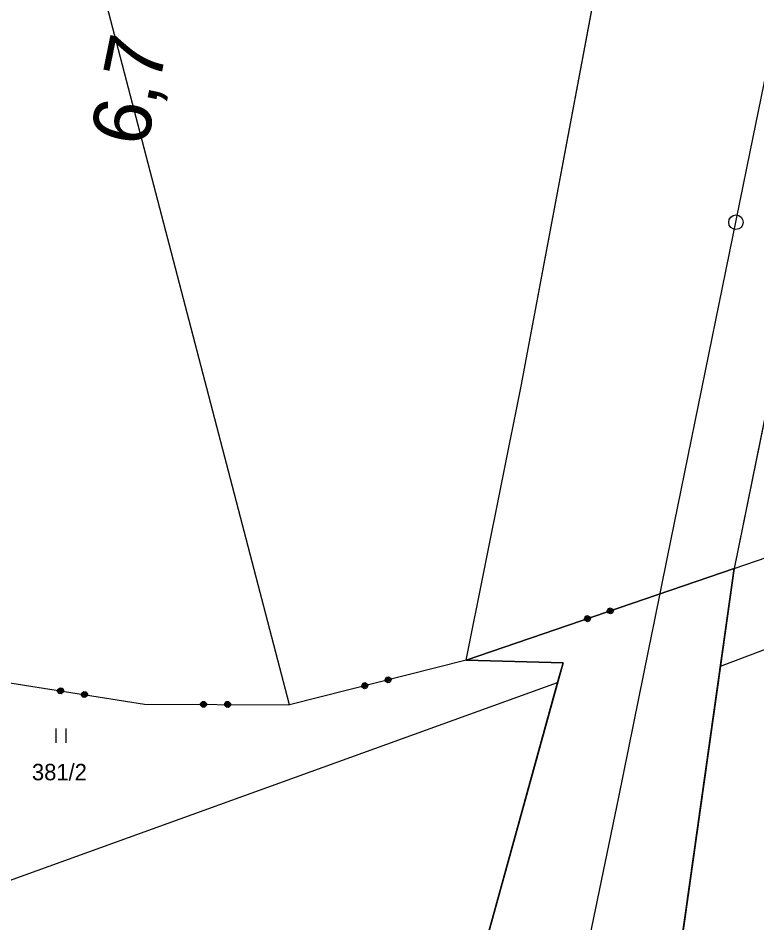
# Model space of a CAD drawing. Extents: x -866656 to -858817, y -1041816 to -1038653.
# Drawn here: x -864198.3 to -864121.9, y -1040985.3 to -1040891.7 of the extents above; entities that cross this region are included whole.
import ezdxf

# ---------------------------------------------------------------- set-up
doc = ezdxf.new("R2010")
doc.units = 0
for name, color, linetype in [('SZDC', 7, 'Continuous'), ('Vrstva 1', 7, 'Continuous'), ('Vrstva 3', 7, 'Continuous'), ('Vrstva 53', 7, 'Continuous'), ('Vrstva 7', 7, 'Continuous')]:
    doc.layers.add(name, color=color, linetype=linetype)

msp = doc.modelspace()

# ---------------------------------------------------------------- linework, layer by layer
at = {"layer": 'SZDC'}
for points in [[(-864079.126, -1040751.242), (-864090.668, -1040816.123), (-864108.728, -1040902.454), (-864114.595, -1040901.24), (-864124.203, -1040948.655), (-864151.935, -1040958.113), (-864146.262, -1040929.775), (-864137.277, -1040882.02), (-864125.279, -1040805.207)], [(-864192.472, -1041180.21), (-864181.025, -1041111.422), (-864180.31, -1041090.767), (-864179.792, -1041075.794), (-864171.697, -1041056.539), (-864163.891, -1041037.972), (-864142.486, -1040960.447), (-864141.92, -1040958.397), (-864151.935, -1040958.113), (-864124.203, -1040948.655), (-864125.631, -1040958.765), (-864138.225, -1041047.925), (-864138.655, -1041084.258), (-864136.94, -1041093.856), (-864135.28, -1041103.15), (-864140.045, -1041118.732), (-864153.013, -1041128.827)]]:
    msp.add_lwpolyline(points, dxfattribs=at)
at = {"layer": 'Vrstva 1'}
for p, q in [((-864170.25, -1040962.74), (-864192.213, -1040878.627)), ((-864146.262, -1040929.775), (-864137.277, -1040882.02)), ((-864114.595, -1040901.24), (-864124.203, -1040948.655)), ((-864151.935, -1040958.113), (-864146.262, -1040929.775)), ((-864138.225, -1041047.925), (-864124.203, -1040948.655)), ((-864125.631, -1040958.765), (-864102.97, -1040950.08)), ((-864141.92, -1040958.397), (-864163.891, -1041037.972)), ((-864151.935, -1040958.113), (-864141.92, -1040958.397)), ((-864202.71, -1040982.19), (-864142.486, -1040960.447)), ((-864194.4, -1040966.69), (-864194.4, -1040965.19)), ((-864193.4, -1040965.19), (-864193.4, -1040966.69))]:
    msp.add_line(p, q, dxfattribs=at)
msp.add_lwpolyline([(-864190.897, -1041239.893), (-864187.654, -1041224.26), (-864179.077, -1041182.252), (-864176.192, -1041168.165), (-864167.631, -1041126.213), (-864158.946, -1041083.668), (-864157.987, -1041079.013), (-864156.213, -1041070.305), (-864147.519, -1041027.821), (-864138.927, -1040985.783), (-864136.16, -1040972.299), (-864133.068, -1040957.148), (-864132.451, -1040954.143), (-864131.095, -1040947.46), (-864122.536, -1040905.522), (-864114.141, -1040864.418), (-864106.236, -1040825.758)], dxfattribs=at)
at = {"layer": 'Vrstva 3'}
for p, q in [((-864124.203, -1040948.655), (-864108.814, -1040943.274)), ((-864124.203, -1040948.655), (-864108.814, -1040943.274)), ((-864124.203, -1040948.655), (-864151.935, -1040958.113)), ((-864124.203, -1040948.655), (-864151.935, -1040958.113)), ((-864137.344, -1040953.031), (-864137.219, -1040952.777)), ((-864137.344, -1040953.031), (-864137.219, -1040952.777)), ((-864137.28, -1040953.221), (-864137.344, -1040953.031)), ((-864137.28, -1040953.221), (-864137.344, -1040953.031)), ((-864137.249, -1040952.999), (-864137.185, -1040953.188)), ((-864137.249, -1040952.999), (-864137.185, -1040953.188)), ((-864137.219, -1040952.777), (-864137.03, -1040952.713)), ((-864137.219, -1040952.777), (-864137.03, -1040952.713)), ((-864137.187, -1040952.872), (-864136.998, -1040952.808)), ((-864137.187, -1040952.872), (-864136.998, -1040952.808)), ((-864137.058, -1040953.251), (-864137.187, -1040952.872)), ((-864137.058, -1040953.251), (-864137.187, -1040952.872)), ((-864137.092, -1040952.84), (-864136.963, -1040953.218)), ((-864137.092, -1040952.84), (-864136.963, -1040953.218)), ((-864137.03, -1040952.713), (-864136.776, -1040952.838)), ((-864137.03, -1040952.713), (-864136.776, -1040952.838)), ((-864136.998, -1040952.808), (-864136.869, -1040953.186)), ((-864136.998, -1040952.808), (-864136.869, -1040953.186)), ((-864136.806, -1040953.059), (-864136.871, -1040952.87)), ((-864136.806, -1040953.059), (-864136.871, -1040952.87)), ((-864136.869, -1040953.186), (-864136.806, -1040953.059)), ((-864136.869, -1040953.186), (-864136.806, -1040953.059)), ((-864136.712, -1040953.027), (-864136.836, -1040953.281)), ((-864136.712, -1040953.027), (-864136.836, -1040953.281)), ((-864136.776, -1040952.838), (-864136.712, -1040953.027)), ((-864136.776, -1040952.838), (-864136.712, -1040953.027)), ((-864139.71, -1040953.838), (-864139.586, -1040953.584)), ((-864139.71, -1040953.838), (-864139.586, -1040953.584)), ((-864139.646, -1040954.028), (-864139.71, -1040953.838)), ((-864139.646, -1040954.028), (-864139.71, -1040953.838)), ((-864139.616, -1040953.806), (-864139.551, -1040953.995)), ((-864139.616, -1040953.806), (-864139.551, -1040953.995)), ((-864139.586, -1040953.584), (-864139.396, -1040953.52)), ((-864139.586, -1040953.584), (-864139.396, -1040953.52)), ((-864139.553, -1040953.679), (-864139.364, -1040953.615)), ((-864139.553, -1040953.679), (-864139.364, -1040953.615)), ((-864139.424, -1040954.058), (-864139.553, -1040953.679)), ((-864139.424, -1040954.058), (-864139.553, -1040953.679)), ((-864139.551, -1040953.995), (-864139.424, -1040954.058)), ((-864139.551, -1040953.995), (-864139.424, -1040954.058)), ((-864139.459, -1040953.647), (-864139.329, -1040954.025)), ((-864139.459, -1040953.647), (-864139.329, -1040954.025)), ((-864139.396, -1040953.52), (-864139.142, -1040953.645)), ((-864139.396, -1040953.52), (-864139.142, -1040953.645)), ((-864139.364, -1040953.615), (-864139.235, -1040953.993)), ((-864139.364, -1040953.615), (-864139.235, -1040953.993)), ((-864139.172, -1040953.866), (-864139.237, -1040953.677)), ((-864139.172, -1040953.866), (-864139.237, -1040953.677)), ((-864139.235, -1040953.993), (-864139.172, -1040953.866)), ((-864139.235, -1040953.993), (-864139.172, -1040953.866)), ((-864139.078, -1040953.834), (-864139.203, -1040954.088)), ((-864139.078, -1040953.834), (-864139.203, -1040954.088)), ((-864139.142, -1040953.645), (-864139.078, -1040953.834)), ((-864139.142, -1040953.645), (-864139.078, -1040953.834)), ((-864137.026, -1040953.345), (-864137.28, -1040953.221)), ((-864137.026, -1040953.345), (-864137.28, -1040953.221)), ((-864137.185, -1040953.188), (-864137.058, -1040953.251)), ((-864137.185, -1040953.188), (-864137.058, -1040953.251)), ((-864136.836, -1040953.281), (-864137.026, -1040953.345)), ((-864136.836, -1040953.281), (-864137.026, -1040953.345)), ((-864139.392, -1040954.152), (-864139.646, -1040954.028)), ((-864139.392, -1040954.152), (-864139.646, -1040954.028)), ((-864139.203, -1040954.088), (-864139.392, -1040954.152)), ((-864139.203, -1040954.088), (-864139.392, -1040954.152)), ((-864151.935, -1040958.113), (-864170.25, -1040962.74)), ((-864151.935, -1040958.113), (-864170.25, -1040962.74)), ((-864199.86, -1040960.37), (-864185.25, -1040962.67)), ((-864199.86, -1040960.37), (-864185.25, -1040962.67)), ((-864162.765, -1040960.746), (-864162.62, -1040960.503)), ((-864162.765, -1040960.746), (-864162.62, -1040960.503)), ((-864162.62, -1040960.503), (-864162.426, -1040960.454)), ((-864162.62, -1040960.503), (-864162.426, -1040960.454)), ((-864162.596, -1040960.6), (-864162.402, -1040960.551)), ((-864162.596, -1040960.6), (-864162.402, -1040960.551)), ((-864162.426, -1040960.454), (-864162.183, -1040960.599)), ((-864162.426, -1040960.454), (-864162.183, -1040960.599)), ((-864162.402, -1040960.551), (-864162.304, -1040960.939)), ((-864162.402, -1040960.551), (-864162.304, -1040960.939)), ((-864160.341, -1040960.134), (-864160.196, -1040959.891)), ((-864160.341, -1040960.134), (-864160.196, -1040959.891)), ((-864160.292, -1040960.328), (-864160.341, -1040960.134)), ((-864160.292, -1040960.328), (-864160.341, -1040960.134)), ((-864160.049, -1040960.472), (-864160.292, -1040960.328)), ((-864160.049, -1040960.472), (-864160.292, -1040960.328)), ((-864160.244, -1040960.109), (-864160.195, -1040960.303)), ((-864160.244, -1040960.109), (-864160.195, -1040960.303)), ((-864160.196, -1040959.891), (-864160.002, -1040959.842)), ((-864160.196, -1040959.891), (-864160.002, -1040959.842)), ((-864160.195, -1040960.303), (-864160.074, -1040960.375)), ((-864160.195, -1040960.303), (-864160.074, -1040960.375)), ((-864160.172, -1040959.988), (-864159.978, -1040959.939)), ((-864160.172, -1040959.988), (-864159.978, -1040959.939)), ((-864160.074, -1040960.375), (-864160.172, -1040959.988)), ((-864160.074, -1040960.375), (-864160.172, -1040959.988)), ((-864160.075, -1040959.963), (-864159.977, -1040960.351)), ((-864160.075, -1040959.963), (-864159.977, -1040960.351)), ((-864159.855, -1040960.423), (-864160.049, -1040960.472)), ((-864159.855, -1040960.423), (-864160.049, -1040960.472)), ((-864160.002, -1040959.842), (-864159.759, -1040959.987)), ((-864160.002, -1040959.842), (-864159.759, -1040959.987)), ((-864159.978, -1040959.939), (-864159.88, -1040960.327)), ((-864159.978, -1040959.939), (-864159.88, -1040960.327)), ((-864159.88, -1040960.327), (-864159.807, -1040960.205)), ((-864159.88, -1040960.327), (-864159.807, -1040960.205)), ((-864159.807, -1040960.205), (-864159.856, -1040960.011)), ((-864159.807, -1040960.205), (-864159.856, -1040960.011)), ((-864159.71, -1040960.181), (-864159.855, -1040960.423)), ((-864159.71, -1040960.181), (-864159.855, -1040960.423)), ((-864159.759, -1040959.987), (-864159.71, -1040960.181)), ((-864159.759, -1040959.987), (-864159.71, -1040960.181)), ((-864194.249, -1040961.354), (-864194.218, -1040961.156)), ((-864194.249, -1040961.354), (-864194.218, -1040961.156)), ((-864194.083, -1040961.583), (-864194.249, -1040961.354)), ((-864194.083, -1040961.583), (-864194.249, -1040961.354)), ((-864194.218, -1040961.156), (-864193.99, -1040960.99)), ((-864194.218, -1040961.156), (-864193.99, -1040960.99)), ((-864194.119, -1040961.172), (-864194.151, -1040961.369)), ((-864194.119, -1040961.172), (-864194.151, -1040961.369)), ((-864194.151, -1040961.369), (-864194.067, -1040961.484)), ((-864194.151, -1040961.369), (-864194.067, -1040961.484)), ((-864194.067, -1040961.484), (-864194.005, -1040961.089)), ((-864194.067, -1040961.484), (-864194.005, -1040961.089)), ((-864194.005, -1040961.089), (-864193.808, -1040961.12)), ((-864194.005, -1040961.089), (-864193.808, -1040961.12)), ((-864193.99, -1040960.99), (-864193.792, -1040961.021)), ((-864193.99, -1040960.99), (-864193.792, -1040961.021)), ((-864193.906, -1040961.104), (-864193.969, -1040961.499)), ((-864193.906, -1040961.104), (-864193.969, -1040961.499)), ((-864193.657, -1040961.447), (-864193.885, -1040961.614)), ((-864193.657, -1040961.447), (-864193.885, -1040961.614)), ((-864193.808, -1040961.12), (-864193.87, -1040961.515)), ((-864193.808, -1040961.12), (-864193.87, -1040961.515)), ((-864193.87, -1040961.515), (-864193.755, -1040961.432)), ((-864193.87, -1040961.515), (-864193.755, -1040961.432)), ((-864193.792, -1040961.021), (-864193.626, -1040961.25)), ((-864193.792, -1040961.021), (-864193.626, -1040961.25)), ((-864193.755, -1040961.432), (-864193.724, -1040961.234)), ((-864193.755, -1040961.432), (-864193.724, -1040961.234)), ((-864193.626, -1040961.25), (-864193.657, -1040961.447)), ((-864193.626, -1040961.25), (-864193.657, -1040961.447)), ((-864191.749, -1040961.545), (-864191.52, -1040961.379)), ((-864191.749, -1040961.545), (-864191.52, -1040961.379)), ((-864191.598, -1040961.873), (-864191.536, -1040961.477)), ((-864191.598, -1040961.873), (-864191.536, -1040961.477)), ((-864191.536, -1040961.477), (-864191.338, -1040961.509)), ((-864191.536, -1040961.477), (-864191.338, -1040961.509)), ((-864191.52, -1040961.379), (-864191.322, -1040961.41)), ((-864191.52, -1040961.379), (-864191.322, -1040961.41)), ((-864191.437, -1040961.493), (-864191.499, -1040961.888)), ((-864191.437, -1040961.493), (-864191.499, -1040961.888)), ((-864191.322, -1040961.41), (-864191.156, -1040961.638)), ((-864191.322, -1040961.41), (-864191.156, -1040961.638)), ((-864162.716, -1040960.94), (-864162.765, -1040960.746)), ((-864162.716, -1040960.94), (-864162.765, -1040960.746)), ((-864162.473, -1040961.085), (-864162.716, -1040960.94)), ((-864162.473, -1040961.085), (-864162.716, -1040960.94)), ((-864162.668, -1040960.721), (-864162.619, -1040960.915)), ((-864162.668, -1040960.721), (-864162.619, -1040960.915)), ((-864162.619, -1040960.915), (-864162.498, -1040960.988)), ((-864162.619, -1040960.915), (-864162.498, -1040960.988)), ((-864162.498, -1040960.988), (-864162.596, -1040960.6)), ((-864162.498, -1040960.988), (-864162.596, -1040960.6)), ((-864162.499, -1040960.575), (-864162.401, -1040960.963)), ((-864162.499, -1040960.575), (-864162.401, -1040960.963)), ((-864162.279, -1040961.036), (-864162.473, -1040961.085)), ((-864162.279, -1040961.036), (-864162.473, -1040961.085)), ((-864162.304, -1040960.939), (-864162.231, -1040960.817)), ((-864162.304, -1040960.939), (-864162.231, -1040960.817)), ((-864162.231, -1040960.817), (-864162.28, -1040960.623)), ((-864162.231, -1040960.817), (-864162.28, -1040960.623)), ((-864162.134, -1040960.793), (-864162.279, -1040961.036)), ((-864162.134, -1040960.793), (-864162.279, -1040961.036)), ((-864162.183, -1040960.599), (-864162.134, -1040960.793)), ((-864162.183, -1040960.599), (-864162.134, -1040960.793)), ((-864193.885, -1040961.614), (-864194.083, -1040961.583)), ((-864193.885, -1040961.614), (-864194.083, -1040961.583)), ((-864191.78, -1040961.743), (-864191.749, -1040961.545)), ((-864191.78, -1040961.743), (-864191.749, -1040961.545)), ((-864191.613, -1040961.971), (-864191.78, -1040961.743)), ((-864191.613, -1040961.971), (-864191.78, -1040961.743)), ((-864191.65, -1040961.561), (-864191.681, -1040961.758)), ((-864191.65, -1040961.561), (-864191.681, -1040961.758)), ((-864191.681, -1040961.758), (-864191.598, -1040961.873)), ((-864191.681, -1040961.758), (-864191.598, -1040961.873)), ((-864191.416, -1040962.002), (-864191.613, -1040961.971)), ((-864191.416, -1040962.002), (-864191.613, -1040961.971)), ((-864191.187, -1040961.836), (-864191.416, -1040962.002)), ((-864191.187, -1040961.836), (-864191.416, -1040962.002)), ((-864191.338, -1040961.509), (-864191.4, -1040961.904)), ((-864191.338, -1040961.509), (-864191.4, -1040961.904)), ((-864191.4, -1040961.904), (-864191.286, -1040961.82)), ((-864191.4, -1040961.904), (-864191.286, -1040961.82)), ((-864191.286, -1040961.82), (-864191.255, -1040961.623)), ((-864191.286, -1040961.82), (-864191.255, -1040961.623)), ((-864191.156, -1040961.638), (-864191.187, -1040961.836)), ((-864191.156, -1040961.638), (-864191.187, -1040961.836)), ((-864179.449, -1040962.597), (-864179.248, -1040962.398)), ((-864179.449, -1040962.597), (-864179.248, -1040962.398)), ((-864179.248, -1040962.398), (-864179.048, -1040962.398)), ((-864179.248, -1040962.398), (-864179.048, -1040962.398)), ((-864179.048, -1040962.398), (-864178.849, -1040962.599)), ((-864179.048, -1040962.398), (-864178.849, -1040962.599)), ((-864176.949, -1040962.608), (-864176.748, -1040962.409)), ((-864176.949, -1040962.608), (-864176.748, -1040962.409)), ((-864176.748, -1040962.409), (-864176.548, -1040962.41)), ((-864176.748, -1040962.409), (-864176.548, -1040962.41)), ((-864176.548, -1040962.41), (-864176.349, -1040962.611)), ((-864176.548, -1040962.41), (-864176.349, -1040962.611)), ((-864185.25, -1040962.67), (-864170.25, -1040962.74)), ((-864185.25, -1040962.67), (-864170.25, -1040962.74)), ((-864179.45, -1040962.797), (-864179.449, -1040962.597)), ((-864179.45, -1040962.797), (-864179.449, -1040962.597)), ((-864179.251, -1040962.998), (-864179.45, -1040962.797)), ((-864179.251, -1040962.998), (-864179.45, -1040962.797)), ((-864179.349, -1040962.597), (-864179.35, -1040962.797)), ((-864179.349, -1040962.597), (-864179.35, -1040962.797)), ((-864179.35, -1040962.797), (-864179.25, -1040962.898)), ((-864179.35, -1040962.797), (-864179.25, -1040962.898)), ((-864179.051, -1040962.998), (-864179.251, -1040962.998)), ((-864179.051, -1040962.998), (-864179.251, -1040962.998)), ((-864179.25, -1040962.898), (-864179.249, -1040962.498)), ((-864179.25, -1040962.898), (-864179.249, -1040962.498)), ((-864179.249, -1040962.498), (-864179.049, -1040962.498)), ((-864179.249, -1040962.498), (-864179.049, -1040962.498)), ((-864179.149, -1040962.498), (-864179.15, -1040962.898)), ((-864179.149, -1040962.498), (-864179.15, -1040962.898)), ((-864178.85, -1040962.799), (-864179.051, -1040962.998)), ((-864178.85, -1040962.799), (-864179.051, -1040962.998)), ((-864179.049, -1040962.498), (-864179.05, -1040962.898)), ((-864179.049, -1040962.498), (-864179.05, -1040962.898)), ((-864179.05, -1040962.898), (-864178.95, -1040962.799)), ((-864179.05, -1040962.898), (-864178.95, -1040962.799)), ((-864178.95, -1040962.799), (-864178.949, -1040962.599)), ((-864178.95, -1040962.799), (-864178.949, -1040962.599)), ((-864178.849, -1040962.599), (-864178.85, -1040962.799)), ((-864178.849, -1040962.599), (-864178.85, -1040962.799)), ((-864176.95, -1040962.808), (-864176.949, -1040962.608)), ((-864176.95, -1040962.808), (-864176.949, -1040962.608)), ((-864176.751, -1040963.009), (-864176.95, -1040962.808)), ((-864176.751, -1040963.009), (-864176.95, -1040962.808)), ((-864176.849, -1040962.609), (-864176.85, -1040962.809)), ((-864176.849, -1040962.609), (-864176.85, -1040962.809)), ((-864176.85, -1040962.809), (-864176.75, -1040962.909)), ((-864176.85, -1040962.809), (-864176.75, -1040962.909)), ((-864176.551, -1040963.01), (-864176.751, -1040963.009)), ((-864176.551, -1040963.01), (-864176.751, -1040963.009)), ((-864176.75, -1040962.909), (-864176.749, -1040962.509)), ((-864176.75, -1040962.909), (-864176.749, -1040962.509)), ((-864176.749, -1040962.509), (-864176.549, -1040962.51)), ((-864176.749, -1040962.509), (-864176.549, -1040962.51)), ((-864176.649, -1040962.51), (-864176.65, -1040962.91)), ((-864176.649, -1040962.51), (-864176.65, -1040962.91)), ((-864176.35, -1040962.811), (-864176.551, -1040963.01)), ((-864176.35, -1040962.811), (-864176.551, -1040963.01)), ((-864176.549, -1040962.51), (-864176.55, -1040962.91)), ((-864176.549, -1040962.51), (-864176.55, -1040962.91)), ((-864176.55, -1040962.91), (-864176.45, -1040962.811)), ((-864176.55, -1040962.91), (-864176.45, -1040962.811)), ((-864176.45, -1040962.811), (-864176.449, -1040962.611)), ((-864176.45, -1040962.811), (-864176.449, -1040962.611)), ((-864176.349, -1040962.611), (-864176.35, -1040962.811)), ((-864176.349, -1040962.611), (-864176.35, -1040962.811))]:
    msp.add_line(p, q, dxfattribs=at)
at = {"layer": 'Vrstva 53'}
for points in [[(-864163.471, -1040355.801), (-864153.108, -1040402.253), (-864151.773, -1040408.236), (-864141.636, -1040383.5), (-864136.164, -1040395.654), (-864121.344, -1040428.573), (-864124.994, -1040437.136), (-864137.005, -1040440.857), (-864126.473, -1040480.602), (-864126.25, -1040482.627), (-864122.508, -1040516.53), (-864121.023, -1040529.985), (-864108.772, -1040562.648), (-864093.709, -1040623.913), (-864080.868, -1040663.902), (-864070.496, -1040699.085), (-864073.496, -1040728.47), (-864078.356, -1040748.127), (-864079.126, -1040751.243), (-864090.668, -1040816.124), (-864108.728, -1040902.455), (-864114.595, -1040901.241), (-864124.203, -1040948.655)], [(-864151.935, -1040958.113), (-864146.262, -1040929.776), (-864137.277, -1040882.021), (-864125.279, -1040805.208), (-864144.051, -1040778.984), (-864138.75, -1040728.981)], [(-864124.203, -1040948.655), (-864125.631, -1040958.765), (-864138.225, -1041047.925), (-864138.655, -1041084.258), (-864136.94, -1041093.856), (-864135.28, -1041103.15), (-864140.045, -1041118.732), (-864153.013, -1041128.827)], [(-864192.472, -1041180.21), (-864181.025, -1041111.422), (-864180.31, -1041090.767), (-864179.792, -1041075.794), (-864171.697, -1041056.539), (-864163.891, -1041037.972), (-864142.486, -1040960.447), (-864141.92, -1040958.397), (-864151.935, -1040958.113)]]:
    msp.add_lwpolyline(points, dxfattribs=at)
at = {"layer": 'Vrstva 7'}
msp.add_circle((-864124.023, -1040912.808), 0.75, dxfattribs=at)

# ---------------------------------------------------------------- texts
at = {"layer": 'Vrstva 1'}
msp.add_text('381/2', height=1.7, dxfattribs=at).set_placement((-864196.903, -1040970.56))
at = {"layer": 'Vrstva 7'}
msp.add_text('6,7', height=6, rotation=78.46508, dxfattribs=at).set_placement((-864185.053, -1040905.167))

doc.saveas('drawing.dxf')
